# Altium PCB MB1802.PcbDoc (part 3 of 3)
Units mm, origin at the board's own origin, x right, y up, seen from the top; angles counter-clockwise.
Board outline 70 x 70 mm, 4 copper layers (Top Layer, Signal Layer 1, Signal Layer 2, Bottom Layer), stack 1.56 mm thick; 220 components, 159 nets, 974 pads, 563 vias.
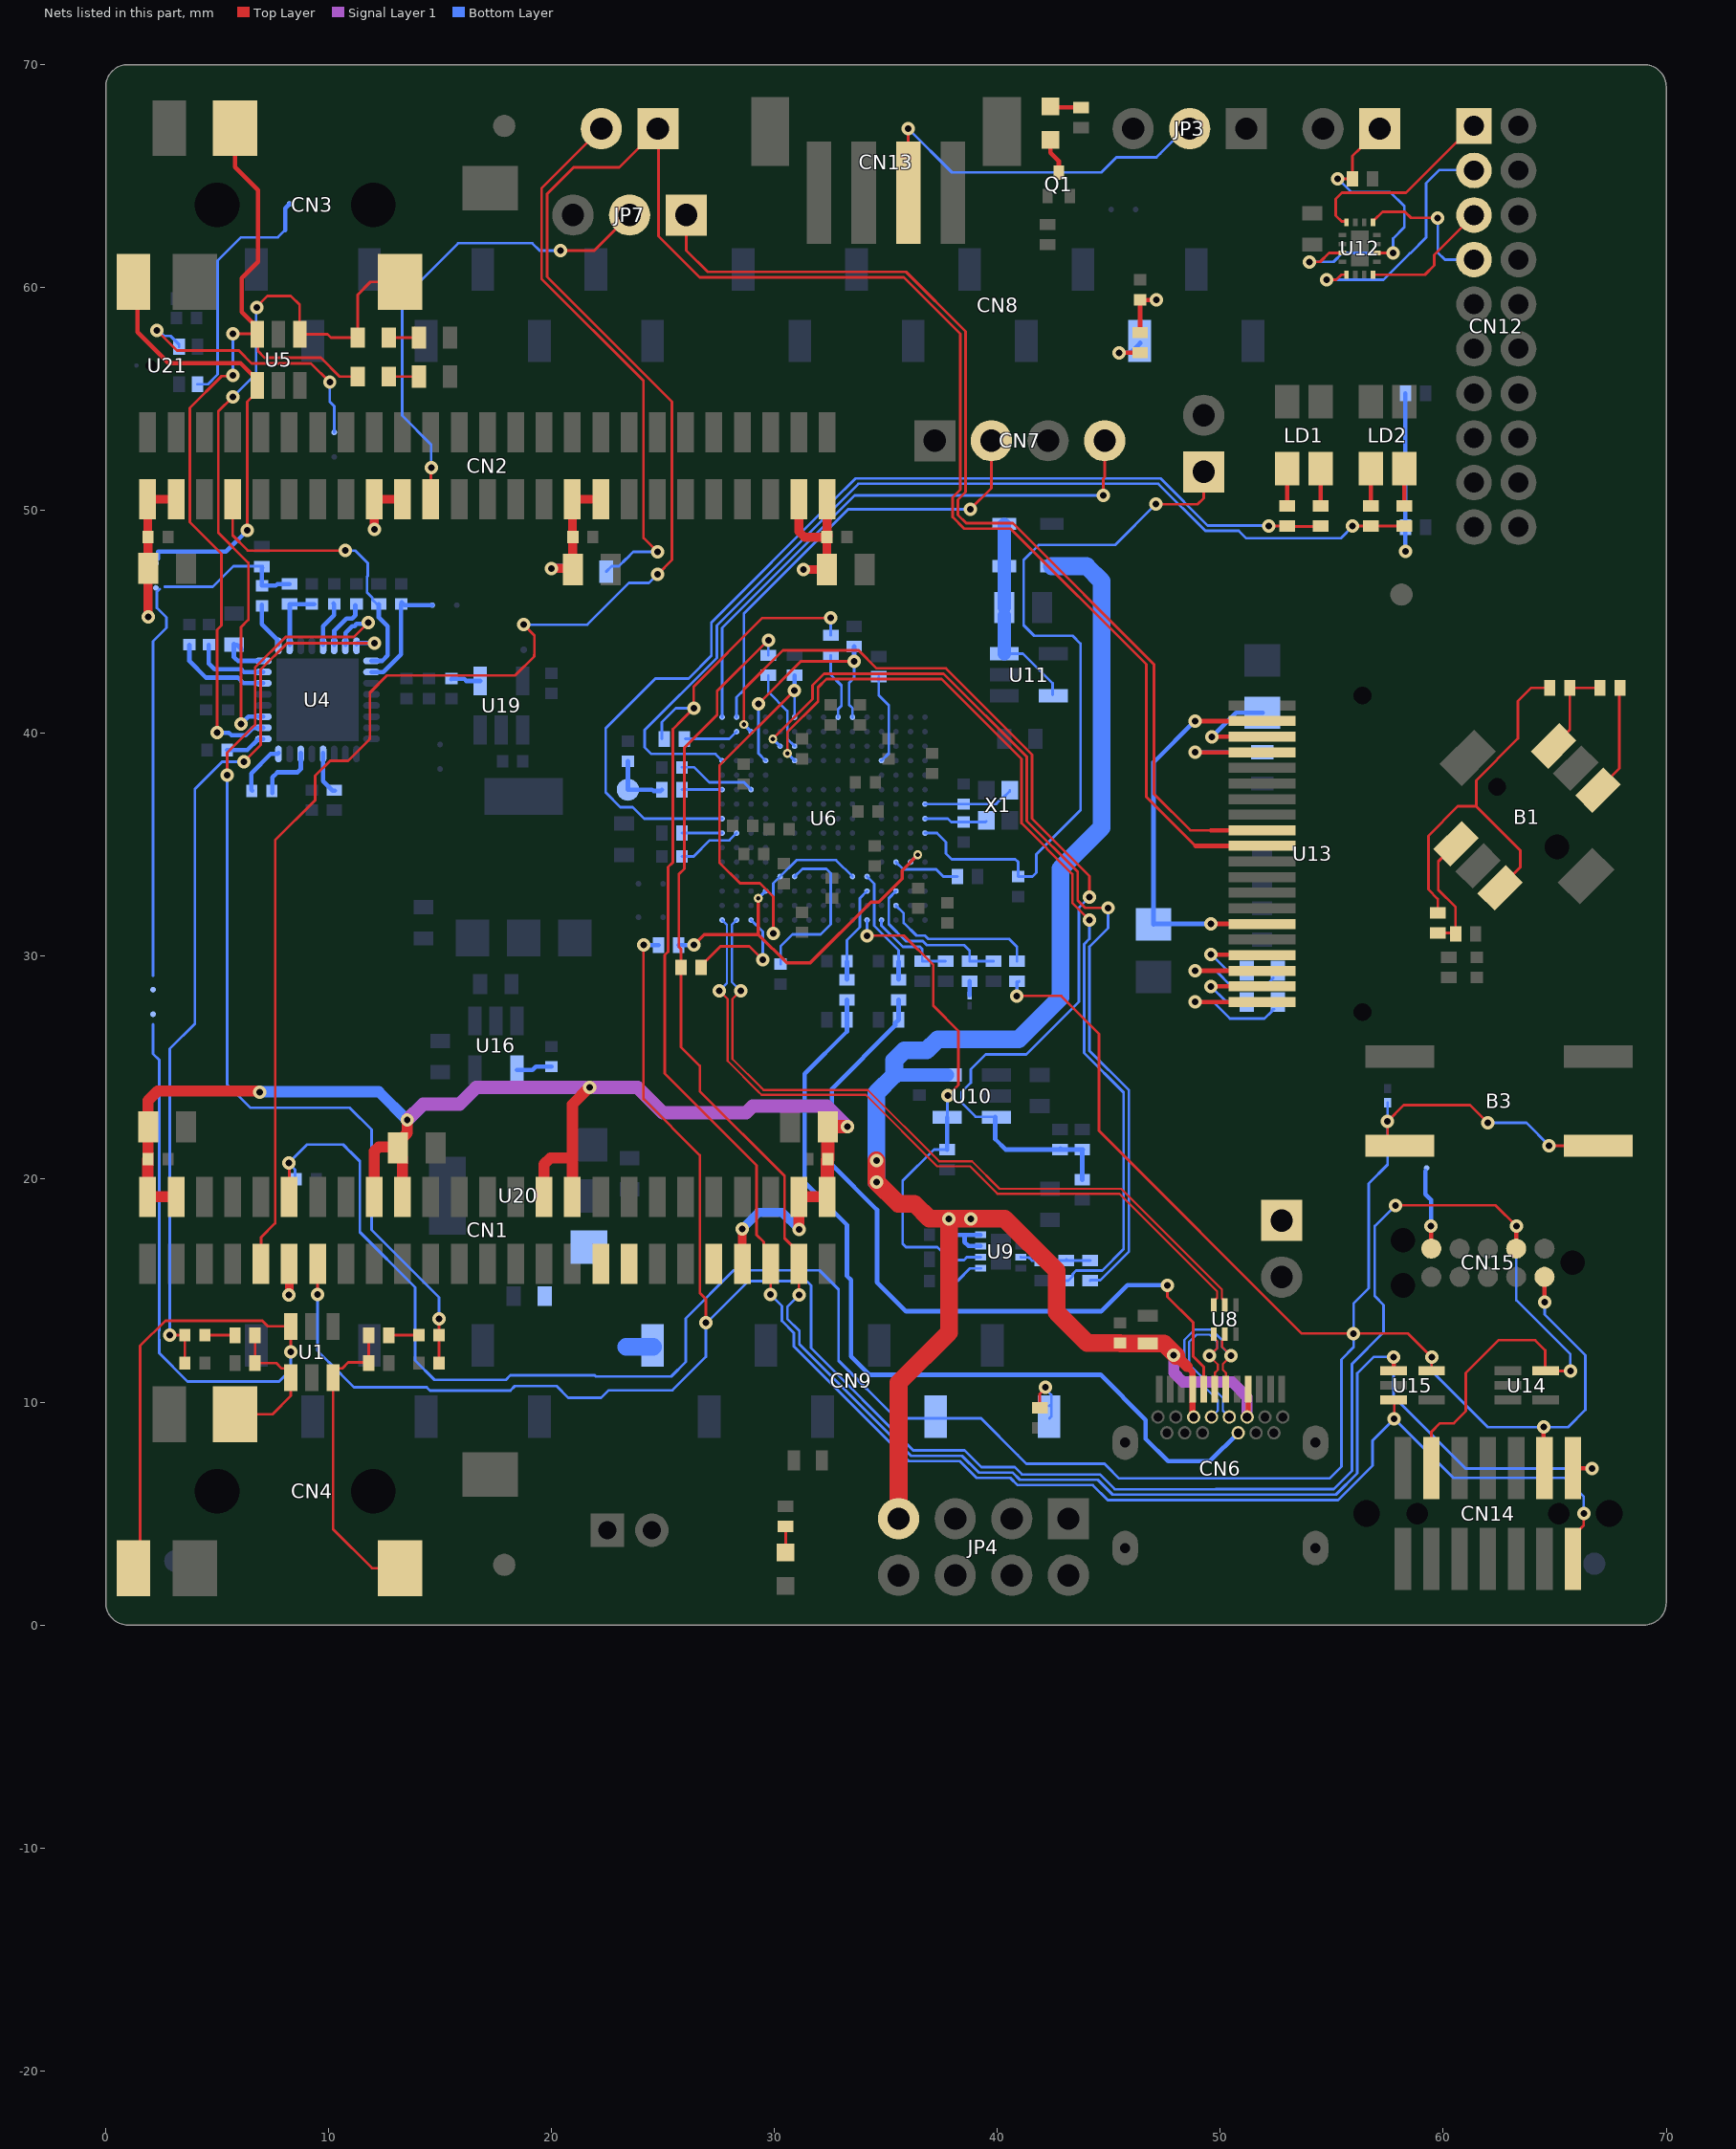
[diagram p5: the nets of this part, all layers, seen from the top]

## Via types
v1: diameter 0.6, hole 0.3, Top Layer to Bottom Layer, 509 vias
v2: diameter 0.4, hole 0.2, Top Layer to Bottom Layer, tented both sides, 54 vias

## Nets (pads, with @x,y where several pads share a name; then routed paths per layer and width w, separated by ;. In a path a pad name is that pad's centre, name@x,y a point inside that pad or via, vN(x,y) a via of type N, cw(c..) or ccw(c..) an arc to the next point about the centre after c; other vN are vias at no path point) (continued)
MCU.SWDIO: CN1.13 CN14.4 CN15.2 R16.2 U14.5 | length 118.2
  Top Layer w0.12: v1(9.5,14.825) 9.505,14.83 CN1.13@9.505,16.21 ; v1(24.125,30.5) 24.125,23.6 26.65,21.075 26.65,14.9 26.925,14.625 v1(26.925,13.555) ; v1(57.85,18.825) 62.35,18.825 v1(63.275,17.9) ; CN14.4@59.46,7.032 59.46,8.66 59.85,9.05 60.472,9.05 61.01,9.588 61.01,11.31 62.475,12.775 64.125,12.775 64.575,12.325 U14.5@64.575,11.35 ; U14.5@64.6,11.4 v1(65.7,11.4)
  Top Layer w0.2: CN15.2@63.275,16.885 v1(63.275,17.9)
  Bottom Layer w0.12: v1(9.5,14.825) 9.5,12.3 9.72,12.08 9.72,12.076 10.001,11.795 10.005,11.795 11.13,10.67 14.401,10.67 14.551,10.52 18.156,10.52 18.353,10.717 20.222,10.717 20.749,10.19 22.226,10.19 22.566,10.53 25.423,10.53 26.925,12.032 v1@26.925,13.525 ; v1(26.925,13.555) v1@26.925,13.525 ; v1(57.85,18.825) 56.925,17.9 56.925,14.75 57.325,14.35 57.325,13.128 55.905,11.708 55.905,6.909 55.091,6.095 49.794,6.095 49.789,6.09 45.267,6.09 44.602,6.755 41.102,6.755 40.777,7.08 39.281,7.08 38.526,7.835 36.219,7.835 31.635,12.419 31.635,15.24 31.445,15.43 28.83,15.43 v1@26.925,13.525 ; v1(63.275,17.9) 63.275,14.575 65.7,12.15 v1(65.7,11.4)
  Bottom Layer w0.2: v1(24.125,30.5) R16.2@24.8,30.5
MCU.VCP_RX: CN1.45 CN14.13 R21.2 R57.2 U15.3 | length 88.9
  Top Layer w0.12: v1(29.825,14.825) CN1.45@29.825,16.21 29.513,16.522 29.513,17.187 29.2,17.5 29.2,20.625 25.08,24.745 25.08,30.051 25.23,30.201 25.23,34.001 25.44,34.211 25.44,40.19 25.875,40.625 v1(26.375,41.125) 26.375,42.1 29.45,45.175 v1(32.525,45.175) ; U15.3@57.75,10.1 57.8,10.05 v1(57.8,9.25) ; CN14.13@65.81,2.968 65.81,3.993 66.08,4.263 66.088,4.263 66.3,4.475 v1(66.3,5)
  Bottom Layer w0.12: R57.2@24.95,39.75 24.95,40.5 25.575,41.125 v1(26.375,41.125) ; v1(29.825,14.825) 30.335,14.315 30.335,13.64 30.875,13.1 30.875,12.5 36.025,7.35 38.311,7.35 39.061,6.6 40.578,6.6 40.903,6.275 44.275,6.275 44.95,5.6 55.275,5.6 56.825,7.15 56.825,8.275 v1(57.8,9.25) 60.45,6.6 65.45,6.6 66.3,5.75 v1(66.3,5) ; R21.2@32.525,44.4 v1(32.525,45.175)
MCU.VCP_TX: CN1.47 CN14.14 R20.2 R58.2 U15.1 | length 84.8
  Top Layer w0.12: v1@29.725,44.2 27.425,41.9 27.425,40.825 25.955,39.355 25.955,33.926 25.71,33.681 25.71,30.415 25.8,30.325 R58.2@25.8,29.5 25.8,25.925 26.65,25.075 26.65,23.95 30.45,20.15 30.45,17.35 30.75,17.05 30.78,17.05 31.095,16.735 31.095,14.805 v1(31.1,14.8)
  Top Layer w0.2: U15.1@57.775,11.35 v1(57.775,12.025) ; CN14.14@65.81,7.032 66.668,7.032 v1(66.675,7.025)
  Bottom Layer w0.12: R20.2@29.725,43.5 v1(29.725,44.175) ; v1(31.1,14.8) 30.575,14.275 30.575,13.739 31.115,13.199 31.115,12.599 36.124,7.59 38.41,7.59 39.16,6.84 40.677,6.84 41.002,6.515 44.502,6.515 45.167,5.85 55.186,5.85 56.145,6.809 56.145,11.295 56.875,12.025 v1(57.775,12.025) 57.775,10.25 61,7.025 v1(66.675,7.025)
MOD1: CN12.1 U12.16 | length 8.9
  Top Layer w0.12: U12.16@55.65,62.925 55.615,62.96 55.44,62.96 55.175,63.225 55.175,63.975 55.45,64.25 58.325,64.25 60.585,66.51 60.635,66.51 61.325,67.2 CN12.1@61.325,67.25
MOD2: CN12.2 U12.5 | length 11
  Top Layer w0.12: v1(54.775,60.35) 55.2,60.35 55.425,60.575 U12.5@55.65,60.575
  Bottom Layer w0.12: v1(54.775,60.35) 57.316,60.35 58.501,61.535 58.514,61.535 59.225,62.246 59.225,64.675 59.825,65.275 CN12.2@61.375,65.275
MOD3: CN12.3 U12.8 | length 5.9
  Top Layer w0.12: U12.8@56.85,60.575 59.175,60.575 59.587,60.987 59.587,61.462 CN12.3@61.375,63.25
MOD4: CN12.4 U12.13 | length 6.5
  Top Layer w0.12: U12.13@56.85,62.925 56.85,63 56.89,63.04 56.915,63.04 57.275,63.4 58.275,63.4 58.55,63.125 v1@59.725,63.125
  Bottom Layer w0.12: v1(59.75,63.125) 59.75,61.575 60.075,61.25 CN12.4@61.375,61.25
NetB1_1: B1.1 R3.1 R4.2 | length 5.5
  Top Layer w0.12: R3.1@59.75,31.05 60.5,31.05 R4.2@60.55,31 60.55,31.05 60.55,32.2 59.775,32.975 59.775,34.25 B1.1@60.575,35.05
NetB1_3: B1.3 R2.1 R3.2 | length 18.4
  Top Layer w0.12: R3.2@59.75,31.95 59.75,32.575 59.33,32.995 59.33,35.405 60.65,36.725 61.468,36.725 63.45,34.743 63.45,33.993 B1.3@62.525,33.068 ; 61.475,36.725 61.475,37.893 63.35,39.768 63.35,41.443 63.95,42.043 64.75,42.043 R2.1@64.775,42.018
NetB1_4: B1.4 R1.1 R2.2 | length 4.2
  Top Layer w0.12: B1.4@64.95,39.443 65.675,40.168 R2.2@65.675,42.043 R1.1@66.975,42.043
NetB1_6: B1.6 R1.2 | length 5
  Top Layer w0.12: B1.6@66.932,37.452 67.9,38.42 R1.2@67.9,42.068
NetC12_1: C12.1 R6.2 | length 1.3
  Top Layer w0.12: R6.2@12.7,13 C12.1@13.975,13
NetC12_2: C12.2 C14.2 U4.23 | length 45.9
  Top Layer w0.12: v1(5.45,38.125) 5.45,39.125 6.7,40.375 6.7,42.95 8.075,44.325 11.136,44.325 v1(11.783,44.972) ; v1(14.95,13.725) C12.2@14.95,13 14.95,11.825 C14.2@14.975,11.8
  Bottom Layer w0.12: v1(5.45,38.125) 5.45,24.25 6.5,23.2 10.95,23.2 11.925,22.225 11.925,17.725 14.95,14.7 v1(14.95,13.725)
  Bottom Layer w0.2: U4.23@10.755,43.975 10.755,44.505 11.055,44.805 11.158,44.805 11.26,44.907 11.718,44.907 v1(11.783,44.972)
NetC21_1: C21.1 R51.1 | length 1.3
  Top Layer w0.12: C21.1@12.7,56 R51.1@14.05,56
NetC21_2: C21.2 CN3.4 U4.10 U5.6 | length 38.9
  Top Layer w0.12: v1(5,40.025) 5,44.65 5.19,44.84 5.19,48.06 3.775,49.475 3.775,54.6 5.2,56.025 5.665,56.025 v1(5.7,56.06) ; v1(5.7,57.925) U5.6@6.799,57.925 ; U5.6@6.8,57.9 6.835,57.865 6.835,57.14 7.125,56.85 9.65,56.85 10.5,56 C21.2@11.3,56
  Top Layer w0.2: CN3.4@5.8,67.15 5.8,65.4 6.825,64.375 6.825,61.15 6.1,60.425 6.1,58.9 6.6,58.4 6.799,58.201 6.8,58.2 U5.6@6.8,57.9
  Bottom Layer w0.12: v1(5.7,56.06) v1(5.7,57.925)
  Bottom Layer w0.2: v1@5.075,40.025 5.525,40.025 5.641,39.909 6.281,39.909 6.622,40.25 U4.10@7.075,40.25
NetC22_1: C22.1 SB8.2 U4.26 | length 5.3
  Bottom Layer w0.2: U4.26@11.925,42.75 12.45,42.75 13.25,43.55 C22.1@13.25,45.8 ; C22.1@13.275,45.875 13.4,45.75 SB8.2@14.65,45.75
NetC23_1: C23.1 R52.1 | length 1.3
  Top Layer w0.12: C23.1@12.7,57.75 R52.1@14.05,57.75
NetC23_2: C23.2 CN3.6 U4.11 U5.4 | length 31.6
  Top Layer w0.12: v1(5.7,55.1) 5.05,54.45 5.05,49 6.4,47.65 6.4,45.1 6.065,44.765 v1(6.065,40.429) ; v1@6.75,59.125 7.25,59.625 8.3,59.625 8.7,59.225 U5.4@8.7,57.9 9.95,57.9 10.1,57.75 C23.2@11.3,57.75 11.3,59.175 11.3,59.675 11.875,60.25 CN3.6@13.2,60.25
  Bottom Layer w0.12: v1(5.7,55.1) 6.75,56.15 v1@6.75,59.125
  Bottom Layer w0.2: v1(6.065,40.429) 6.079,40.429 6.4,40.75 U4.11@7.075,40.75
  other v1: 6.775,59.1
NetC24_2: C24.2 U4.9 | length 1.8
  Bottom Layer w0.2: C24.2@5.45,39.25 6.35,39.25 6.85,39.75 U4.9@7.075,39.75
NetC25_1: C25.1 U4.8 | length 2.4
  Bottom Layer w0.2: C25.1@6.575,37.425 6.525,37.475 6.525,38.2 7.4,39.075 7.704,39.075 U4.8@7.754,39.125
NetC25_2: C25.2 U4.6 | length 2.9
  Bottom Layer w0.2: C25.2@7.475,37.325 7.475,38.025 7.7,38.25 8.6,38.25 8.755,38.405 U4.6@8.755,39.125
NetC26_1: C26.1 R53.1 R54.1 SB6.1 SB7.2 | length 24.7
  Bottom Layer w0.12: 2.125,29.125 2.125,29.575 ; 2.125,29.58 2.125,44.125 2.725,44.725 2.725,45.2 2.3,45.625 2.3,46.35 2.425,46.475 ; 2.65,46.575 4.8,46.575 5.725,47.5 R53.1@7.05,47.5
  Bottom Layer w0.2: R53.1@7.025,47.425 7.005,47.405 C26.1@7.005,46.625 7.625,46.625 7.7,46.7 R54.1@8.25,46.7
NetC26_2: C26.2 U4.17 | length 2.1
  Bottom Layer w0.2: C26.2@7,45.775 7,44.898 7.716,44.182 7.716,44.014 U4.17@7.755,43.975
NetC27_1: C27.1 R54.2 U4.18 | length 2.9
  Bottom Layer w0.2: R54.2@8.25,45.8 R54.2@8.275,45.8 ; U4.18@8.255,43.975 8.255,45.78 R54.2@8.275,45.8 ; C27.1@9.35,45.8 C27.1@9.25,45.8 R54.2@8.275,45.8
NetC28_2: C28.2 U4.15 | length 3.5
  Bottom Layer w0.2: C28.2@4.625,43.975 4.625,43.125 4.875,42.875 6.075,42.875 6.2,42.75 U4.15@7.075,42.75
NetC29_2: C29.2 U4.22 | length 2.3
  Bottom Layer w0.2: U4.22@10.255,43.975 10.255,44.605 10.8,45.15 11.05,45.15 11.2,45.3 C29.2@11.2,45.75
NetC30_2: C30.2 U4.21 | length 2.1
  Bottom Layer w0.2: U4.21@9.755,43.975 9.755,44.805 10.25,45.3 C30.2@10.25,45.8 C30.2@10.225,45.825
NetC31_2: C31.2 U4.16 | length 2.3
  Bottom Layer w0.2: C31.2@5.75,44 5.75,43.425 5.825,43.35 5.875,43.3 5.925,43.25 U4.16@7.075,43.25 ; C31.2@5.88,43.975 C31.2@6.1,43.755
NetC32_2: C32.2 U4.14 | length 4.5
  Bottom Layer w0.2: C32.2@3.755,43.975 3.755,43.245 4.5,42.5 5.925,42.5 6.173,42.252 7.073,42.252 U4.14@7.075,42.25
NetC36_2: C36.2 R12.2 TP1.1 | length 3
  Bottom Layer w0.2: C36.2@23.425,38.75 TP1.1@23.425,37.475 ; TP1.1@23.55,37.475 TP1.1@23.425,37.475 ; R12.2@24.95,37.475 24.894,37.419 24.569,37.419 24.512,37.475 TP1.1@23.425,37.475
NetC42_2: C42.2 U6.J14 | length 2.9
  Bottom Layer w0.12: C42.2@25.85,34.475 26.375,34.475 27.1,35.2 27.975,35.2 U6.J14@28.3,35.525
NetC45_2: C45.2 U9.1 | length 1.6
  Bottom Layer w0.12: C45.2@37.925,15.4 37.965,15.44 38.215,15.44 38.775,16 U9.1@39.25,16
NetC48_2: C48.2 U6.M10 | length 7.6
  Bottom Layer w0.12: C48.2@30.275,29.65 30.275,30.45 30.8,30.975 32.075,30.975 32.525,31.425 32.525,33.73 32.33,33.925 31.25,33.925 U6.M10@30.9,33.575
NetC49_2: C49.2 U6.F13 | length 3.5
  Bottom Layer w0.12: C49.2@25.85,38.475 26.4,38.475 27.075,37.8 28.625,37.8 U6.F13@28.95,37.475
NetC59_2: C59.2 D1.2 D2.2 U11.3 U11.5 | length 8.7
  Bottom Layer w0.12: U11.3@40.305,43.575 41.15,43.575 42.475,42.25 U11.5@42.475,41.725
  Bottom Layer w0.6: U11.3@40.305,43.575 C59.2@40.305,45.28 ; C59.2@40.305,45.65 D1.2@40.305,47.5 D2.2@40.305,49.37
NetC71_1: C71.1 U13.2 | length 4.1
  Top Layer w0.2: v1(49.575,28.65) U13.2@51.875,28.65
  Bottom Layer w0.12: v1(49.575,28.65) 50.25,27.975 C71.1@51.075,27.975
NetC71_2: C71.2 U13.1 | length 7
  Top Layer w0.2: v1(48.875,27.95) U13.1@51.875,27.95
  Bottom Layer w0.12: v1(48.875,27.95) 49.675,27.95 50.425,27.2 51.975,27.2 52.315,27.54 52.315,27.565 52.375,27.625 C71.2@52.4,27.625
NetC72_1: C72.1 U13.3 | length 6.9
  Top Layer w0.2: v1(48.875,29.35) U13.3@51.875,29.35
  Bottom Layer w0.12: v1(48.875,29.35) 48.885,29.34 49.81,29.34 50.5,28.65 52,28.65 52.315,28.965 C72.1@52.375,29.025
NetC72_2: C72.2 U13.4 | length 4.2
  Top Layer w0.2: v1(49.575,30.075) 51.85,30.075 U13.4@51.875,30.05
  Bottom Layer w0.12: v1@49.575,30.1 50.325,29.35 C72.2@51.175,29.35
NetC73_1: C73.1 U13.6 U13.19 | length 17.8
  Top Layer w0.2: v1(48.875,40.55) U13.19@51.875,40.55 ; v1(49.575,31.45) U13.6@51.875,31.45
  Bottom Layer w0.2: C73.1@47,31.425 47,38.7 v1@48.9,40.6 ; C73.1@47.025,31.475 47.05,31.45 v1(49.575,31.45)
NetC76_1: C76.1 U13.18 | length 5
  Top Layer w0.2: v1(49.625,39.85) U13.18@51.875,39.85
  Bottom Layer w0.2: v1(49.625,39.85) 50.7,40.925 C76.1@51.875,40.925 C76.1@51.9,40.925
NetC79_1: C79.1 U16.4 | length 1.6
  Bottom Layer w0.2: U16.4@18.45,24.9 19.15,24.9 19.3,25.05 C79.1@20,25.05
NetC82_2: C82.2 U19.4 | length 1.4
  Bottom Layer w0.2: C82.2@15.5,42.425 15.525,42.45 16.075,42.45 16.175,42.35 U19.4@16.8,42.35
NetC87_1: C87.1 C88.2 U4.24 | length 40.5
  Top Layer w0.12: v1(2.875,13) C88.2@3.55,13 C87.1@3.55,11.75 ; v1(6.2,38.725) 6.95,39.475 6.95,42.861 8.139,44.05 v1(12.05,44.05)
  Bottom Layer w0.12: v1(2.875,13) 2.875,25.85 4,26.975 4,37.5 5.225,38.725 v1(6.2,38.725)
  Bottom Layer w0.2: U4.24@11.255,44.004 11.255,44.009 11.296,44.05 v1(12.05,44.05)
NetC88_1: C88.1 R50.2 | length 1.3
  Top Layer w0.12: C88.1@4.45,13 R50.2@5.8,13
NetCN2_7: CN2.7 R55.1 U4.25 | length 13.6
  Top Layer w0.12: CN2.7@5.695,50.5 5.695,48.88 6.375,48.2 v1(10.75,48.2)
  Bottom Layer w0.12: v1(10.75,48.2) 11.187,48.2 11.75,47.637 11.75,47.06 11.72,47.03 11.72,46.33 11.96,46.09 11.96,45.995 12.155,45.8 R55.1@12.25,45.8
  Bottom Layer w0.2: U4.25@11.925,43.25 12.4,43.25 12.65,43.5 12.65,44.8 12.25,45.2 R55.1@12.25,45.8
NetCN3_2: CN3.2 SB7.1 U5.1 | length 20.3
  Top Layer w0.12: v1(6.35,49.1) 6.35,54.875 6.55,55.075 6.56,55.075 6.8,55.315 U5.1@6.8,55.6
  Top Layer w0.2: CN3.2@1.25,60.25 1.426,60.074 1.426,57.999 2.825,56.6 6.05,56.6 6.55,56.1 6.6,56.1 6.8,55.9 U5.1@6.8,55.6
  Bottom Layer w0.2: 2.35,47.825 2.35,48.15 5.4,48.15 v1(6.35,49.1)
NetCN4_2: CN4.2 SB6.2 U1.6 | length 40.9
  Top Layer w0.12: CN4.2@1.25,2.55 1.55,2.85 1.55,12.525 2.675,13.65 7.025,13.65 7.275,13.4 U1.6@8.3,13.4 v1(8.3,12.25)
  Bottom Layer w0.12: 2.125,26.95 2.125,25.625 2.4,25.35 2.4,13.204 2.395,13.199 2.395,12.801 2.4,12.796 2.4,12.2 3.675,10.925 7.775,10.925 8.3,11.45 v1(8.3,12.25)
NetCN4_4: CN4.4 R10.2 R50.1 U1.1 | length 6.9
  Top Layer w0.12: CN4.4@5.8,9.45 7.475,9.45 8.3,10.275 U1.1@8.3,11.1 8.3,11.27 8.06,11.51 7.89,11.51 7.65,11.75 R10.2@6.7,11.75 R50.1@6.7,13
NetCN4_6: CN4.6 R6.1 R7.1 U1.3 | length 13.7
  Top Layer w0.12: R6.1@11.75,13 11.8,12.95 R7.1@11.8,11.75 ; R7.1@11.775,11.775 10.875,11.775 10.61,11.51 10.44,11.51 10.2,11.27 U1.3@10.2,11.1 10.2,4.3 11.95,2.55 CN4.6@13.2,2.55
NetCN6_A5: CN6.A5 R11.1 R13.2 | length 34.1
  Top Layer w0.12: v1(47.625,15.225) 47.625,14.725 48.775,13.575 48.775,12.05 49.25,11.575 CN6.A5@49.25,10.58
  Bottom Layer w0.2: R13.2@35.57,28.05 R11.1@35.57,27.15 35.415,26.995 35.415,26.89 32.575,24.05 32.575,20.65 34.6,18.625 34.6,15.375 35.9,14.075 44.65,14.075 45.825,15.25 47.6,15.25 v1(47.625,15.225)
NetCN6_B5: CN6.B5 R14.2 R15.1 | length 38
  Bottom Layer w0.2: R14.2@33.25,28.05 R15.1@33.25,27.15 33.25,26.625 31.35,24.725 31.35,19.85 33.25,17.95 33.25,15.65 33.425,15.475 33.425,12.043 34.243,11.225 44.625,11.225 46.65,9.2 46.65,8.35 47.65,7.35 49.53,7.35 CN6.B5@50.8,8.62
NetCN8_8: CN8.8 R44.1 | length 2.1
  Top Layer w0.2: v1(45.45,57.075) R44.1@46.398,57.075
  Bottom Layer w0.2: v1(45.45,57.075) 45.988,57.075 46.398,57.485 CN8.8@46.398,57.525
NetCN9_1: CN9.1 R43.1 | length 2.6
  Top Layer w0.12: R43.1@41.9,9.75 41.9,10.365 42.15,10.615 v1(42.15,10.675)
  Bottom Layer w0.12: v1@42.175,10.65 42.175,10.571 42.417,10.329 42.417,9.35 CN9.1@42.334,9.267 ; CN9.1@42.325,9.825 CN9.1@42.35,9.85
NetCN13_3: CN13.3 JP3.2 | length 16.2
  Top Layer w0.12: v1(36,67.125) 36,65.25 CN13.3@36.075,65.175
  Bottom Layer w0.12: v1(36,67.125) 37.961,65.164 44.664,65.164 45.339,65.839 47.136,65.839 47.301,66.005 47.305,66.005 48.425,67.125 JP3.2@48.625,67.125
NetCN15_5: CN15.5 SB1.1 | length 3.6
  Top Layer w0.2: v1(59.45,17.9) 59.45,16.895 CN15.5@59.46,16.885
  Bottom Layer w0.2: 59.2,20.375 59.2,19.325 59.375,19.15 59.45,19.075 v1(59.45,17.9)
NetJP2_1: JP2.1 R45.2 U12.3 U12.10 | length 15.3
  Top Layer w0.12: v1(54,61.15) 54.475,61.15 54.875,61.55 U12.3@55.475,61.55 ; v1(55.25,64.875) R45.2@55.925,64.875 55.925,65.9 56.28,66.255 56.28,66.26 57.045,67.025 JP2.1@57.05,67.025 ; U12.10@57.025,61.55 57.675,61.55 v1@57.7,61.575
  Bottom Layer w0.12: v1(54,61.15) 55.075,61.15 55.475,61.55 v1@57.675,61.55 ; v1@55.275,64.875 55.875,64.275 57.625,64.275 58.25,63.65 58.25,62.7 57.75,62.2 v1(57.75,61.55)
NetJP6_2: JP6.2 R5.2 | length 24.9
  Top Layer w0.12: JP6.2@22.23,67.125 19.55,64.445 19.55,60.386 24.125,55.811 24.125,48.765 v1(24.75,48.14)
  Bottom Layer w0.12: R5.2@22.45,47.25 22.7,47.5 23.021,47.5 23.351,47.83 23.355,47.83 23.665,48.14 v1(24.75,48.14)
NetLD1_1: LD1.1 R35.1 | length 1.6
  Top Layer w0.12: R35.1@54.5,50.325 R35.1@54.525,50.3
  Top Layer w0.2: R35.1@54.5,50.325 LD1.1@54.5,51.875
NetLD1_2: LD1.2 R36.1 | length 1.6
  Top Layer w0.12: R36.1@52.975,50.275 R36.1@53,50.3
  Top Layer w0.2: R36.1@53,50.3 LD1.2@53,51.875
NetLD2_1: LD2.1 R37.1 | length 1.6
  Top Layer w0.12: R37.1@58.175,50.275 R37.1@58.25,50.35
  Top Layer w0.2: R37.1@58.25,50.35 LD2.1@58.25,51.875
NetLD2_2: LD2.2 R38.2 | length 1.7
  Top Layer w0.12: R38.2@56.75,50.25 R38.2@56.8,50.2
  Top Layer w0.2: R38.2@56.75,50.25 LD2.2@56.75,51.875
NetLD3_1: LD3.1 R41.2 | length 1.4
  Top Layer w0.2: LD3.1@42.375,68.125 42.425,68.075 R41.2@43.725,68.075
NetLD3_2: LD3.2 Q1.3 | length 1.6
  Top Layer w0.2: LD3.2@42.375,66.625 42.375,66.05 42.75,65.675 Q1.3@42.75,65.225
NetLD4_1: LD4.1 R48.1 | length 1.2
  Top Layer w0.12: LD4.1@30.5,3.25 R48.1@30.5,4.425
NetR12_1: R12.1 U6.F15 | length 1.8
  Bottom Layer w0.12: R12.1@25.85,37.475 U6.F15@27.65,37.475
NetR24_1: R24.1 U6.P3 | length 7.1
  Bottom Layer w0.12: U6.P3@35.45,32.275 35.795,31.93 35.795,31.499 36.369,30.925 36.739,30.925 36.889,30.775 40.525,30.775 40.875,30.425 R24.1@40.875,29.775
NetR25_1: R25.1 U6.J15 | length 1.8
  Bottom Layer w0.12: R25.1@25.85,35.525 U6.J15@27.65,35.525
NetR28_1: R28.1 U6.D4 | length 4.1
  Bottom Layer w0.12: R28.1@34.675,42.55 34.675,41.7 35.125,41.25 35.125,39.1 U6.D4@34.8,38.775
NetR31_1: R31.1 R32.1 R33.1 U9.7 | length 3.2
  Bottom Layer w0.12: U9.7@41.05,16.5 41.06,16.49 41.41,16.49 41.545,16.355 41.995,16.355 R33.1@42,16.35 ; R33.1@42.005,16.35 43.05,16.35 R31.1@43.1,16.4 ; R31.1@43.08,16.35 R32.1@44.155,16.35 R32.1@44.175,16.35
NetR46_2: R46.2 U13.17 | length 6
  Top Layer w0.2: v1(48.875,39.15) U13.17@51.875,39.15
  Bottom Layer w0.2: v1(48.875,39.15) 51.8,39.15 R46.2@51.825,39.175
NetR49_1: R49.1 U4.4 | length 2
  Bottom Layer w0.2: U4.4@9.755,39.125 9.755,37.85 10.18,37.425 R49.1@10.275,37.425
NetR57_1: R57.1 U6.B14 | length 2.4
  Bottom Layer w0.12: R57.1@26,39.75 27.975,39.75 U6.B14@28.3,40.075
NetR58_1: R58.1 U6.R13 | length 5.3
  Top Layer w0.12: R58.1@26.775,29.65 26.775,29.67 26.895,29.79 26.915,29.79 27.575,30.45 28.875,30.45 v1(29.475,29.85)
  Bottom Layer w0.12: U6.R13@28.95,31.625 29.47,31.105 29.47,30.826 29.475,30.821 v1(29.475,29.85)
NetSB3_1: SB3.1 U21.1 | length 11
  Bottom Layer w0.12: U21.1@4.114,55.662 4.587,55.662 5.025,56.1 5.025,61.2 6.075,62.25 7.725,62.25 8.05,62.575
  Bottom Layer w0.2: 8.05,62.575 8.05,63.55 SB3.1@8.25,63.75
NetSB4_1: SB4.1 U21.4 | length 12.4
  Top Layer w0.12: v1(2.3,58.075) 3.2,57.175 5.975,57.175 6.55,56.6 9.2,56.6 v1(10.05,55.75)
  Bottom Layer w0.12: v1(2.3,58.075) 2.36,58.075 2.61,57.825 2.906,57.825 3.292,57.439 U21.4@3.292,57.338 ; v1(10.05,55.75) 10.05,54.875 10.25,54.675 SB4.1@10.25,53.5
NRST: B3.1 B3.2 C15.2 CN1.12 CN9.3 CN14.12 CN15.10 R24.2 U3.1 U15.5 | length 141.5
  Top Layer w0.12: v1(8.225,20.725) 8.235,20.715 CN1.12@8.235,19.21 ; v1(40.875,28.22) 42.855,28.22 44.55,26.525 44.55,22.175 53.65,13.075 v1(55.975,13.075) 58.425,13.075 v1(59.475,12.025) U15.5@59.475,11.45 ; B3.2@57.475,21.7 57.5,21.725 v1(57.5,22.6) 58.225,23.325 61.2,23.325 v1(62,22.525) ; v1(64.75,21.5) B3.1@66.95,21.5 B3.1@66.975,21.5
  Top Layer w0.2: v1(64.5,8.875) 64.5,7.975 CN14.12@64.525,7.95 ; CN15.10@64.535,15.62 64.535,14.49 v1(64.55,14.475)
  Bottom Layer w0.12: v1@8.225,20.775 v1(8.225,20.725) 8.225,20.696 8.5,20.421 C15.2@8.5,20 ; v1@8.25,20.775 9.025,21.55 10.65,21.55 10.969,21.231 10.973,21.231 11.4,20.804 11.4,17.625 13.875,15.15 13.875,11.875 14.75,11 17.957,11 18.154,11.197 21.944,11.197 21.991,11.15 25.364,11.15 26.015,11.801 26.015,13.754 28.171,15.91 32.015,15.91 32.875,15.05 32.875,11.858 35.466,9.267 39.269,9.267 40.916,7.62 41.301,7.235 44.801,7.235 44.885,7.151 45.461,6.575 54.892,6.575 55.425,7.108 55.425,11.907 55.975,12.457 v1(55.975,13.075) 55.975,14.425 56.65,15.1 56.65,19.8 57.5,20.65 v1(57.5,22.6) U3.1@57.5,23.438 ; R24.2@40.95,28.85 R24.2@40.975,28.875 ; v1(59.475,12.025) 59.475,11.4 62,8.875 v1(64.5,8.875) 65.6,8.875 66.375,9.65 66.375,12.1 64.55,13.925 v1(64.55,14.475) ; v1(62,22.525) 63.725,22.525 v1(64.75,21.5)
  Bottom Layer w0.15: v1(40.875,28.22) R24.2@40.875,28.85
OLED.CS: CN1.9 JP6.1 U13.11 | length 122.6
  Top Layer w0.12: CN1.9@6.965,16.21 6.965,17.39 7.6,18.025 7.6,35.2 9.4,37 9.4,38.1 10.07,38.77 10.878,38.77 11.845,39.737 11.845,39.789 11.85,39.794 11.85,41.825 12.625,42.6 18.375,42.6 19.225,43.45 19.225,43.521 19.23,43.526 19.23,44.395 v1(18.75,44.875) ; v1(24.75,47.125) 25.4,47.775 25.4,54.875 19.8,60.475 19.8,64.2 20.99,65.39 23.035,65.39 JP6.1@24.77,67.125 24.8,67.095 24.8,62.3 26.64,60.46 35.801,60.46 38.335,57.926 38.335,50.935 37.985,50.585 37.985,49.701 38.501,49.185 40.59,49.185 46.675,43.1 46.675,37.15 48.875,34.95
  Top Layer w0.2: 48.875,34.95 U13.11@51.875,34.95
  Bottom Layer w0.12: v1(18.75,44.875) 21.6,44.875 23.475,46.75 24.375,46.75 v1(24.75,47.125)
OLED.RST: JP7.1 U13.12 | length 47.4
  Top Layer w0.12: JP7.1@26.04,63.75 26.04,61.66 27,60.7 35.9,60.7 38.575,58.025 38.575,50.825 38.225,50.475 38.225,49.8 38.6,49.425 40.689,49.425 47.025,43.089 47.025,37.275 48.65,35.65 49.575,35.65
  Top Layer w0.2: 49.575,35.65 U13.12@51.875,35.65
OSC32_IN: CN1.33
OSC32_OUT: CN1.35
OSC_OUT: CN1.41
PA12: CN2.21 JP7.2 | length 21.6
  Top Layer w0.12: CN2.21@14.585,50.5 14.585,51.91 v1(14.6,51.925) ; v1(20.4,61.66) 21.91,61.66 JP7.2@23.5,63.25
  Bottom Layer w0.12: v1(14.6,51.925) 14.6,52.95 13.3,54.25 13.3,59.475 15.81,61.985 19.14,61.985 19.465,61.66 v1(20.4,61.66)
STLK_LED: R37.2 R38.1 U6.D15 | length 45.2
  Top Layer w0.12: v1(55.925,49.3) R38.1@56.75,49.3 58.225,49.3 R37.2@58.25,49.325
  Bottom Layer w0.12: U6.D15@27.65,38.775 27.35,39.075 24.475,39.075 24.175,39.375 24.175,40.15 27.41,43.385 27.41,44.835 33.77,51.195 47.216,51.195 49.326,49.085 50.826,49.085 51.161,48.75 55.4,48.75 v1@55.925,49.275
STLK_NRST: C41.2 JP1.1 U6.J1 | length 33.9
  Top Layer w0.12: v1@47.125,50.275 48.975,50.275 49.25,50.55 JP1.1@49.25,51.73
  Bottom Layer w0.12: U6.J1@36.75,35.525 37.29,35.525 37.69,35.125 37.69,34.605 37.945,34.35 40.804,34.35 40.925,34.229 C41.2@40.925,33.575 41.575,33.575 41.75,33.75 41.75,34.575 43.725,36.55 43.725,44.025 43.375,44.375 41.65,44.375 41.175,44.85 41.175,47.775 41.85,48.45 45.275,48.45 v1(47.109,50.284)
STLK_OSC_IN: C39.1 U6.G1 X1.1 | length 4.1
  Bottom Layer w0.12: U6.G1@36.75,36.825 C39.1@38.48,36.825 39.93,36.825 40.055,36.95 40.055,36.955 40.185,37.085 40.235,37.085 40.55,37.4 X1.1@40.55,37.45
STLK_OSC_OUT: C40.2 U6.H1 X1.3 | length 2.8
  Bottom Layer w0.12: U6.H1@36.75,36.175 37.775,36.175 37.925,36.025 C40.2@38.48,36.025 39.425,36.025 39.475,36.025 X1.3@39.5,36.05
STLK_SWCLK: CN7.2 U6.A14 | length 20.4
  Top Layer w0.12: v1(38.775,50.05) 39.725,51 CN7.2@39.725,53.175
  Bottom Layer w0.12: U6.A14@28.3,40.725 28.3,41.625 28.625,41.95 28.625,45.371 33.304,50.05 v1(38.775,50.05)
STLK_SWDIO: CN7.4 U6.A15 | length 26
  Top Layer w0.12: v1@44.75,50.7 44.75,51.425 44.81,51.485 CN7.4@44.81,53.125
  Bottom Layer w0.12: U6.A15@27.65,40.725 27.65,43.525 27.65,44.736 33.589,50.675 v1(44.75,50.675)
STLK_UCPD_CC1_C: C37.1 R13.1 U6.M5 | length 5.2
  Bottom Layer w0.12: U6.M5@34.15,33.575 34.475,33.25 34.475,31.361 35.57,30.266 35.57,30.235
  Bottom Layer w0.125: C37.1@35.57,29.775 35.57,30.235
  Bottom Layer w0.2: R13.1@35.57,28.95 C37.1@35.57,29.775
STLK_UCPD_CC2_C: C38.1 R14.1 U6.N5 | length 4.3
  Bottom Layer w0.12: C38.1@33.25,29.775 33.25,30.725 33.825,31.3 33.825,32.6 U6.N5@34.15,32.925
  Bottom Layer w0.2: R14.1@33.25,28.95 C38.1@33.25,29.775
STLK_USB_CN_N: CN6.A7 CN6.B7 U8.2 | length 9.9
  Top Layer w0.1: U8.2@50.2,12.9 50.2,12.875 50.075,12.75 50.075,12.475 v1(50.475,12.075) 50.11,11.71 50.11,11.447 50.25,11.307 CN6.A7@50.25,10.58
  Bottom Layer w0.1: CN6.B7@49.6,9.33 49.89,9.62 49.89,10.09 48.38,11.6 48.38,12.791 48.834,13.245 49.616,13.245 50.073,12.789 50.073,12.477 v1(50.475,12.075)
STLK_USB_CN_P: CN6.A6 CN6.B6 U8.1 | length 8.9
  Top Layer w0.1: v1@49.508,12.067 49.89,11.685 49.89,11.447 49.75,11.307 CN6.A6@49.75,10.58 ; v1@49.678,12.238 49.855,12.415 49.855,12.736 49.791,12.8 49.775,12.8 49.725,12.85 U8.1@49.725,12.925
  Bottom Layer w0.1: v1(49.515,12.075) 49.853,12.412 49.853,12.697 49.525,13.025 48.925,13.025 48.6,12.7 48.6,11.691 50.11,10.181 50.11,9.62 CN6.B6@50.4,9.33
STLK_USB_N: U6.R14 U8.5 | length 33.6
  Top Layer w0.1: v1(28.485,28.45) 28.115,28.08 28.115,25.396 29.406,24.106 29.511,24 34.186,24 37.386,20.8 38.861,20.8 40.091,19.57 45.555,19.57 50.07,15.055 50.07,14.655 50.2,14.525 U8.5@50.2,14.35
  Bottom Layer w0.1: U6.R14@28.3,31.625 28.085,31.41 28.085,28.85 v1(28.485,28.45)
STLK_USB_P: U6.R15 U8.6 | length 33.6
  Top Layer w0.1: v1(27.525,28.45) 27.895,28.08 27.895,25.305 29.25,23.95 29.42,23.78 34.095,23.78 37.295,20.58 38.77,20.58 40,19.35 45.464,19.35 49.85,14.964 49.85,14.675 49.7,14.525 U8.6@49.7,14.35
  Bottom Layer w0.1: v1(27.525,28.45) 27.865,28.79 27.865,31.41 U6.R15@27.65,31.625
STLK_VCP_RX: R20.1 U6.C10 | length 3.7
  Bottom Layer w0.12: R20.1@29.725,42.6 29.725,41.937 29.725,41.85 30.575,41 30.575,39.75 U6.C10@30.9,39.425
STLK_VCP_TX: R21.1 U6.A7 | length 3
  Bottom Layer w0.12: R21.1@32.525,43.5 32.525,43.065 32.525,42.629 33.005,42.149 33.005,41.23 32.85,41.075 U6.A7@32.85,40.725
T_JTDI: R19.1 U6.L3 | length 3
  Bottom Layer w0.12: U6.L3@35.45,34.225 35.775,33.9 37.25,33.9 37.575,33.575 R19.1@38.2,33.575
T_PWR_EN: R34.2 R40.2 U6.R5 U9.2 U10.4 | length 22.3
  Top Layer w0.12: v1(34.15,30.925) 35.8,30.925 37.125,29.6 37.125,27.775 38.25,26.65 38.25,24.225 v1(37.775,23.75)
  Bottom Layer w0.12: v1(34.15,30.925) U6.R5@34.15,31.625 ; R40.2@37.75,21.325 37.15,21.325 35.75,19.925 35.75,17.1 35.9,16.95 37.3,16.95 37.56,16.69 37.655,16.69 37.85,16.495 R34.2@37.85,16.4 ; U10.4@37.76,22.79 37.76,23.735 v1(37.775,23.75) ; R34.2@37.975,16.375 38.5,16.375 38.625,16.5 U9.2@39.25,16.5
  Bottom Layer w0.2: R40.2@37.75,21.32 U10.4@37.75,22.775
T_PWR_EXT: R22.1 R23.1 U6.R4 | length 4.1
  Bottom Layer w0.12: U6.R4@34.8,31.625 34.8,31.375 35.758,30.418 36.533,30.418 36.625,30.325 R22.1@36.625,29.775 R23.1@37.675,29.775
T_PWR_INT: R29.2 R30.1 R39.2 U6.B13 U10.3 | length 46
  Top Layer w0.12: v2(28.625,40.4) 28.625,41.975 30.375,43.725 33.775,43.725 34.585,42.915 37.689,42.915 41.555,39.049 41.555,36.17 44.125,33.6 v1(44.125,32.65)
  Bottom Layer w0.12: U10.3@39.9,22.8 39.025,22.8 38.4,23.425 38.4,23.924 38.8,24.324 38.8,24.925 39.475,25.6 41.3,25.6 43.65,27.95 43.65,32.175 v1(44.125,32.65) ; R30.1@43.805,21.325 R30.1@43.825,21.325
  Bottom Layer w0.15: v2(28.625,40.4) U6.B13@28.95,40.075
  Bottom Layer w0.2: U10.3@39.9,22.8 39.9,21.8 40.375,21.325 R39.2@42.8,21.325 ; R39.2@42.825,21.375 42.875,21.325 R30.1@43.805,21.325 ; R29.2@43.805,19.975 43.805,21.305 R30.1@43.825,21.325
T_PWR_LED: R35.2 R36.2 U6.H15 | length 47.1
  Top Layer w0.12: v1(52.175,49.3) R36.2@53,49.3 ; R36.2@53.025,49.275 54.475,49.275 R35.2@54.5,49.3
  Bottom Layer w0.12: 26.425,36.175 24.15,36.175 23.638,36.687 23.088,36.687 22.425,37.35 22.425,40.225 24.66,42.46 26.146,42.46 27.17,43.484 27.17,44.97 32.61,50.41 33.635,51.435 47.315,51.435 49.425,49.325 v1@52.2,49.325 ; 26.428,36.178 26.43,36.175 U6.H15@27.65,36.175
T_PWR_SEL1: R31.2 U6.D10 | length 42.1
  Top Layer w0.12: v2(30.575,39.1) 30.575,40.05 31.95,41.425 31.95,42.061 32.324,42.435 37.49,42.435 41.075,38.85 41.075,35.971 43.36,33.686 43.36,32.39 44.125,31.625 v1(44.13,31.625)
  Bottom Layer w0.12: R31.2@43.08,15.45 43.175,15.45 43.37,15.645 43.37,15.74 43.53,15.9 44.7,15.9 45.66,16.86 45.66,23.89 43.89,25.66 43.89,30.54 44.13,30.78 v1(44.13,31.625)
  Bottom Layer w0.15: v2(30.575,39.1) U6.D10@30.9,38.775
T_PWR_SEL2: R32.2 U6.C11 | length 42.6
  Top Layer w0.12: v2(29.925,39.75) 31.71,41.535 31.71,42.16 32.225,42.675 37.589,42.675 41.315,38.949 41.315,36.071 43.6,33.786 43.6,32.496 43.926,32.17 44.275,32.17 44.276,32.171 v1(44.957,32.171)
  Bottom Layer w0.12: R32.2@44.155,15.45 44.17,15.465 44.615,15.465 45.9,16.75 45.9,23.989 44.13,25.759 44.13,30.43 44.957,31.257 v1(44.957,32.171)
  Bottom Layer w0.15: v2(29.925,39.75) U6.C11@30.25,39.425
T_SWCLK: R18.1 U6.A10 U6.M6 U6.M11 | length 22.2
  Top Layer w0.12: v1(29.95,31.025) 29.95,32.675 29.35,33.275 28.455,33.275 27.53,34.2 27.53,38.555 v1(30.9,41.925)
  Bottom Layer w0.12: v1(29.95,31.025) 29.95,31.57 29.945,31.575 29.945,33.27 U6.M11@30.25,33.575 30.988,34.313 32.762,34.313 U6.M6@33.5,33.575 ; U6.A10@30.9,40.725 v1(30.9,41.925)
  Bottom Layer w0.2: v1(30.9,41.925) R18.1@30.9,42.6
T_SWDIO: R16.1 U6.L2 U6.N12 | length 16.2
  Top Layer w0.15: v1(26.375,30.5) 26.85,30.975 29.275,30.975 ; v2(29.275,32.6) 29.275,30.975 ; v2(36.425,34.55) 35.725,33.85 35.725,33.475 34.675,32.425 34.325,32.425 31.6,29.7 30.55,29.7 29.275,30.975
  Bottom Layer w0.15: v2(29.275,32.6) U6.N12@29.6,32.925 ; U6.L2@36.1,34.225 v2(36.425,34.55)
  Bottom Layer w0.2: R16.1@25.7,30.5 v1(26.375,30.5)
T_SWO: R17.1 U6.A6 U6.D12 | length 11.1
  Top Layer w0.12: v1(29.275,41.325) 31.18,43.23 v1(33.575,43.23)
  Bottom Layer w0.12: v1(29.275,41.325) 29.275,39.1 U6.D12@29.6,38.775 ; U6.A6@33.5,40.725 33.5,41.125 33.345,41.28 33.345,42.27 33.575,42.5 v1(33.575,43.23)
  Bottom Layer w0.2: v1(33.575,43.23) R17.1@33.575,43.9
T_VCC: LNK1.2 R26.2 | length 0.6
  Bottom Layer w0.2: LNK1.2@38.75,28.25 R26.2@38.75,28.875
T_VCC_AIN: R26.1 R27.1 U6.N3 | length 7.3
  Bottom Layer w0.12: U6.N3@35.45,32.925 35.125,32.6 35.125,31.443 35.893,30.675 36.65,30.675 36.825,30.5 38.5,30.5 38.75,30.25 R26.1@38.75,29.775 R27.1@39.825,29.775
V1: C1.1 C2.2 C3.2 C4.2 C5.2 C6.2 C7.2 C8.1 C9.2 C10.2 C11.2 C69.1 CN1.2 CN1.4 CN1.11 CN1.18 CN1.20 CN1.30 CN1.32 CN1.43 CN1.48 CN1.50 CN2.1 CN2.3 CN2.17 CN2.19 CN2.31 CN2.33 CN2.47 CN2.49 JP5.1 R5.1 R8.2 R9.2 R44.2 | length 99.7
  Top Layer w0.12: R44.2@46.398,58.027 R44.2@46.425,58
  Top Layer w0.2: R44.2@46.398,57.975 46.398,58.027 C69.1@46.398,59.44 47.115,59.44 v1(47.125,59.45)
  Top Layer w0.4: v1(1.9,45.225) C4.2@1.9,47.4 C9.2@1.9,48.8 1.885,48.815 CN2.1@1.885,50.5 CN2.3@3.155,50.5 CN2.3@3.125,50.47 ; v1(8.225,14.8) 8.235,14.81 CN1.11@8.235,16.21 ; v1(12.05,49.15) 12.045,49.155 CN2.17@12.045,50.5 CN2.19@13.315,50.5 ; v1(20,47.4) 20.9,47.4 C5.2@20.95,47.35 C10.2@20.95,48.75 ; C10.2@20.95,48.8 C10.2@20.95,48.75 ; C10.2@20.975,48.725 C10.2@20.95,48.75 ; CN2.33@22.205,50.5 CN2.31@20.935,50.5 20.935,48.765 C10.2@20.95,48.75 ; v1(28.55,17.775) 28.555,17.77 CN1.43@28.555,16.21 ; CN2.47@31.095,50.5 31.095,49.055 31.35,48.8 32.325,48.8 C11.2@32.365,48.84 ; v1(31.3,47.35) C6.2@32.35,47.35 ; C6.2@32.25,47.175 32.35,47.275 C11.2@32.35,48.8 ; CN2.49@32.365,50.5 C11.2@32.365,48.84 ; C11.2@32.4,48.875 C11.2@32.365,48.84
  Top Layer w0.5: C2.2@1.9,22.35 C2.2@1.9,22.5 ; CN1.4@3.155,19.21 CN1.2@1.885,19.21 1.885,20.885 C7.2@1.9,20.9 C2.2@1.9,22.5 ; v1(6.9,23.9) 6.873,23.9 6.823,23.95 2.325,23.95 1.9,23.525 C2.2@1.9,22.5 ; CN1.18@12.045,19.21 12.045,21.245 12.25,21.45 13.05,21.45 13.05,21.2 13.315,20.935 CN1.20@13.315,19.21 ; C1.1@13.1,21.4 13.1,21.65 13.525,22.075 v1(13.525,22.65) ; CN1.30@19.665,19.21 19.665,20.665 19.95,20.95 20.935,20.95 ; CN1.32@20.935,19.21 20.935,20.95 ; v1@21.681,24.106 20.935,23.36 20.935,20.95 ; v1(31.1,17.75) 31.095,17.755 CN1.48@31.095,19.21 CN1.50@32.365,19.21
  Top Layer w0.6: CN1.50@32.365,19.21 32.365,20.865 C8.1@32.4,20.9 C3.2@32.4,22.35 v1(33.275,22.35)
  Signal Layer 1 w0.6: v1(13.525,22.65) 14.25,23.375 15.875,23.375 16.625,24.125 v1(21.7,24.125) 23.85,24.125 25,22.975 28.725,22.975 29.025,23.275 32.35,23.275 v1(33.275,22.35)
  Bottom Layer w0.2: v1(58.3,48.17) R9.2@58.3,49.25 R8.2@58.3,55.25
  Bottom Layer w0.4: v1@20.05,47.375 20.075,47.4 20.93,47.4 21.05,47.28 R5.1@21.05,47.25 ; v1(28.55,17.775) 29.275,18.5 30.35,18.5 v1(31.1,17.75)
  Bottom Layer w0.5: v1(6.9,23.9) 6.919,23.919 6.99,23.919 6.996,23.925 12.25,23.925 v1(13.525,22.65)
VBUS_STLK: C35.1 C44.2 C46.2 CN6.A4 CN6.A9 CN6.B4 CN6.B9 D1.1 JP4.7 U7.1 U9.3 U9.4 U10.5 | length 84.6
  Top Layer w0.2: CN6.B9@48.75,9.375 CN6.B9@48.775,9.35 ; CN6.B4@51.1,9.375 51.11,9.375 51.25,9.515 CN6.A9@51.25,10.58
  Top Layer w0.28: 48.5,11.6 48.75,11.35 CN6.A4@48.75,10.58 CN6.B9@48.75,9.375
  Top Layer w0.5: v1(47.91,12.1) 47.929,12.081 48.019,12.081 48.5,11.6
  Top Layer w0.8: v1(34.575,19.875) 35.55,18.9 36.275,18.9 36.95,18.225 v1(37.825,18.225) ; v1@34.575,19.925 v1(34.575,20.835) ; JP4.7@35.565,4.77 35.565,10.865 37.825,13.125 v1(37.825,18.225) ; C35.1@45.475,12.65 44.025,12.65 42.65,14.025 42.65,15.9 40.325,18.225 v1(37.825,18.225) ; C35.1@45.5,12.65 45.525,12.625 U7.1@46.75,12.625 47.475,12.625 v1@48.019,12.081
  Signal Layer 1 w0.5: v1(47.91,12.1) 47.91,11.315 48.325,10.9 50.525,10.9 51.2,10.225 CN6.B4@51.2,9.33
  Bottom Layer w0.2: v1(37.825,18.225) 37.85,18.2 C44.2@37.85,17.5 38.525,17.5 ; U9.3@39.25,17 38.7,17 38.525,17.175 38.525,17.5 ; U9.4@39.25,17.5 38.525,17.5
  Bottom Layer w0.6: 35.675,24.675 C46.2@36.5,24.675 U10.5@37.75,24.675
  Bottom Layer w0.8: v1(34.575,19.875) v1(34.575,20.835) 34.575,23.875 35.375,24.675 35.375,25.325 35.825,25.775 36.825,25.775 37.325,26.275 40.95,26.275 42.825,28.15 42.825,33.925 44.675,35.775 44.675,46.825 44,47.5 D1.1@42.445,47.5
  other v1: 38.8,18.225
VIN: C83.2 CN9.8 U20.3 | length 1.2
  Bottom Layer w0.8: 23.35,12.475 23.353,12.472 CN9.8@24.554,12.472
pads on no net: B1.NPTH1 B1.NPTH2 CART_4L.1 CN1.3 CN1.5 CN1.8 CN1.10 CN1.16 CN1.19 CN1.21 CN1.23 CN1.27 CN1.39 CN2.4 CN2.5 CN2.6 CN2.16 CN2.18 CN2.23 CN2.36 CN3.5 CN3.7 CN3.MT1 CN3.MT2 CN4.5 CN4.7 CN4.MT1 CN4.MT2 CN6.A2 CN6.A3 CN6.A8 CN6.A10 CN6.A11 CN6.B2 CN6.B3 CN6.B8 CN6.B10 CN6.B11 CN12.8 CN12.9 CN13.0 CN14.0 CN14.1 CN14.2 CN15.7 CN15.11 CN15.12 CN15.13 MIRE-1.1 MIRE-2.1 MIRE-3.1 MIRE-4.1 MIRE-5.1 MIRE-6.1 U4.19 U4.20 U6.A1 U6.A2 U6.A3 U6.A4 U6.A5 U6.A8 U6.A9 U6.A11 U6.A12 U6.A13 U6.B1 U6.B2 U6.B3 U6.B4 U6.B5 U6.B6 U6.B7 U6.B8 U6.B9 U6.B10 U6.B11 U6.B12 U6.B15 U6.C2 U6.C3 U6.C4 U6.C12 U6.C13 U6.C14 U6.C15 U6.D1 U6.D2 U6.D3 U6.D11 U6.D13 U6.D14 U6.E1 U6.E2 U6.E3 U6.E4 U6.E12 U6.E13 U6.E14 U6.E15 U6.F1 U6.F4 U6.F14 U6.G4 U6.G14 U6.G15 U6.H2 U6.H3 U6.H4 U6.H14 U6.J2 U6.J3 U6.J4 U6.K1 U6.K2 U6.K3 U6.K12 U6.K13 U6.K14 U6.K15 U6.L1 U6.L12 U6.L13 U6.L14 U6.L15 U6.M2 U6.M3 U6.M4 U6.M7 U6.M12 U6.M13 U6.M14 U6.M15 U6.N2 U6.N4 U6.N6 U6.N7 U6.N11 U6.N15 U6.P2 U6.P4 U6.P5 U6.P6 U6.P7 U6.P8 U6.P9 U6.P10 U6.P11 U6.P12 U6.P13 U6.P14 U6.P15 U6.R2 U6.R3 U6.R6 U6.R7 U6.R8 U6.R9 U6.R10 U6.R11 U6.R12 U8.4 U11.4 U12.17 U13.H1 U21.6

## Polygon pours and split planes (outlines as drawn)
GND on Bottom Layer "GND_L04" (solid, remove dead copper, pour order 19): 0,0 0,70 70,70 70,0
3V6 on Bottom Layer "5V_L04_P-001" (solid, pour order 18): 16.84,23.675 14.866,23.675 14.59,23.951 14.59,25.095 16.84,25.095
5V_VIN on Bottom Layer "5V_VIN_L04" (solid, pour order 11): 16.25,16.5 16.25,16 20.25,16 20.25,18 20.75,18.5 24,18.5 24,20 20.75,20 20.25,20.5 20.25,22.5 18.5,22.5 18,23 15.5,23 14.5,22 14.5,16.5
VIN on Bottom Layer "VIN_L04" (solid, pour order 10): 19.5,15 19.5,15.25 20,15.75 20.5,15.75 20.75,16 20.75,17.25 21,17.5 23,17.5 24.75,15.75 24.75,11.75 20.5,11.75 19.5,12.75
3V3 on Bottom Layer "3V3_L04_P-001" (solid, pour order 9): 19.5,32.25 22,32.25 22,36 21.5,36 21.5,40.5 18.5,40.5 18.5,38 17,38 17,36 15.5,36 15.5,32.25 18,32.25 18,30.5 19.5,30.5
5V on Bottom Layer "5V_L04_P-001" (solid, pour order 8): 16.75,26.75 15.75,26.75 13.75,28.75 13.75,31 14.5,31 14.75,31.25 15,31.5 17,31.5 17,28.25 16.75,28
5V on Bottom Layer "5V_L04" (solid, pour order 6): 32.75,10 34.5,8.25 34.5,7.25 34.25,7 32.5,7 31.75,7.75 31.75,10
VBUS_STLK on Bottom Layer "VBUS_STLK_L01" (solid, pour order 2): 39.45,16.9 39.45,18.3 39.25,18.5 37.5,18.5 37.5,17.35 37.8,17.05 38.45,17.05 38.6,16.9
5V_STLK on Bottom Layer "5V_STLK_L04" (solid, pour order 3): 40.85,16.9 40.85,18.1 41.25,18.5 42.85,18.5 43.55,19.2 44.05,19.2 44.5,18.75 44.5,17.25 44.15,16.9 41.9,16.9
5V_STLK on Signal Layer 1 "5V_STLK_L02" (solid, remove dead copper, pour order 13): 42.5,3.75 42.5,17.5 43.5,18.5 44.75,18.5 45.25,18 45.25,4.5 44.5,3.75
GND on Signal Layer 1 "GND_L02_P021" (solid, remove dead copper, pour order 21): 64.5,70 64.5,48.5 64,48 61.25,48 61.25,15 57.75,11.5 46.75,11.5 45.5,10.25 45.5,0 70,0 70,69.75 69.75,70
GND on Signal Layer 1 "GND_L02_P020" (solid, remove dead copper, pour order 20): 0,70 0,46.5 1.75,46.5 17.25,62 59.75,62 60.25,62.5 60.25,70
5V_VIN on Signal Layer 1 "5V_VIN_L02" (solid, remove dead copper, pour order 12): 42,17.75 43.25,19 54,19 57.75,22.75 57.75,47.25 55.25,49.75 43.25,49.75 43.25,31 46.5,31 51,26.5 51,23.25 36.75,23.25 16.5,23.25 16,22.75 16,20.75 19.5,17.25 19.5,12.5 21.75,10.25 34.5,10.25 35.25,9.5 35.25,7.25 36,6.5 39,6.5 39.25,6.25 39.25,4.25 39.75,3.75 41.5,3.75 42,4.25
5V on Signal Layer 1 "5V_L02_P-001" (solid, remove dead copper, pour order 7): 10,14 10,1 44.25,1 44.75,1.5 44.75,3 44.25,3.5 35,3.5 34.75,3.75 34.75,9.25 34.25,9.75 21.25,9.75 19,12 19,17 15.5,20.5 15.5,23 16.25,23.75 50.5,23.75 50.5,26.5 46.5,30.5 10.5,30.5 7.75,27.75 7.75,16.25
V1 on Signal Layer 1 "3V3_MCU_L02" (solid, remove dead copper, pour order 14): 1,45 17.5,61.5 60.75,61.5 60.75,15.5 57.5,12.25 46.75,12.25 46.75,18.5 54.25,18.5 58.25,22.5 58.25,47.5 57.75,48 57.75,57 57,57.75 36.75,57.75 32,53 32,47.25 27.5,42.75 27.5,31 10.25,31 7.25,28 7.25,16.25 9.5,14 9.5,1 1,1
3V3_STLK on Signal Layer 1 "3V3_STLK_L02" (solid, remove dead copper, pour order 4): 30.5,45 32.5,47 32.5,52.5 37.25,57.25 51.75,57.25 56.75,57.25 57.25,56.75 57.25,52.25 55.25,50.25 43.25,50.25 42.75,49.75 42.75,31 28,31 28,42.5
GND on Top Layer "GND_L01" (solid, remove dead copper, pour order 17): 0,0 0,70 70,70 70,0
5V on Top Layer "5V_L01" (solid, pour order 16): 49,25.25 56,25.25 56,24.75 55,23.75 49,23.75
5V on Top Layer "g" (solid, pour order 5): 32,7 32,8.25 32.38,8.63 34.12,8.63 34.5,8.25 34.5,6.25 33.5,6.25 32.75,7
GND on Signal Layer 2 "GND_L01_P-001" (solid, remove dead copper, pour order 0): 0,70 70,70 70,0 69.5,0.5 0,0.5

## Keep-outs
Keep-Out Layer:
  rectangle: 62.5,45.375 68.625,47.125

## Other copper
Top Layer:
  text "1" at 62.764,45.607 h2
Signal Layer 1:
  text "2" at 64.198,45.607 h2
Signal Layer 2:
  text "3" at 65.831,45.618 h2
  text ".Layer_Name" at 0.025,-14.036 h3
  text ".G2" at 41.725,-14.042 h3
Bottom Layer:
  text "4" at 67.431,45.609 h2

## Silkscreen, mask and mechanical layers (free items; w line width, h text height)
Top Overlay:
  lines w0.15: 2.5,13.75 4.6,13.75 5.1,13.25 5.1,12.5 5.35,12.25
  text "AUDIO_OUT" at 7.8,67.75 h1.5
  text "STLK" at 60.259,51.975 h1.4 r90
  text "PW_ST" at 51.951,51.325 h1.4 r90
  text "RESERVED" at 37.675,50.567 h1.5
  text "J" at 40.2,14.3 h12 r90
  text "MB1802B" at 41.4,13.275 h2 r90
  text "VBUS_STLK" at 35.951,6.501 h1.4 r90
  text "5V_EXT" at 38.451,6.5 h1.4 r90
  text "5VVIN" at 41.084,6.5 h1.4 r90
  text "5V_STLK" at 43.551,6.5 h1.4 r90
  text "AUDIO_IN" at 5.6,0.975 h1.5
Bottom Overlay:
  text "D10 CS / PWM" at 34.7,70.141 h1.5 r90
  text "D11 MOSI / PWM" at 37.4,70.141 h1.5 r90
  text "D13 SCK" at 41.783,67.484 h1.5 r90
  text "D9 MISO" at 39.183,67.352 h1.5 r90
  text "D9 PWM" at 31.483,67.159 h1.5 r90
  text "GND" at 44.1,64.9 h1.4 r90
  text "D14 / SDA" at 49.9,64.693 h1.4 r90
  text "D15 / SCL" at 52.7,64.3 h1.4 r90
  text "D8" at 29.1,63.7 h1.4 r90
  text "D6" at 22.5,57.869 h1.4 r90
  text "D2" at 12.3,56.7 h1.4 r90
  text "D4" at 17.4,56.7 h1.4 r90
  text "D0 / Rx" at 7.9,56.4 h1.4 r90
  text "D1 / Tx" at 10.4,56.4 h1.4 r90
  text "D3 / PWM" at 15.3,56.4 h1.4 r90
  text "D5 / PWM" at 20.5,56.4 h1.4 r90
  text "D7" at 25,56.4 h1.4 r90
  text "VREFP" at 46.9,56.4 h1.4 r90
  text "UK / CA" at 62.425,38.875 h5
  text "G" at 63.175,30.3 h10
  text "F" at 11.675,27.35 h12
  text "I" at 6.25,18 h12
  text "A5" at 7.2,16.537 h1.5 r90
  text "A4" at 9.8,15.277 h1.5 r90
  text "A3" at 12.283,15.281 h1.5 r90
  text "A2" at 14.7,15.271 h1.5 r90
  text "A1" at 17.3,15.095 h1.5 r90
  text "A0" at 19.783,13.978 h1.5 r90
  text "IOREF" at 40.283,9.3 h1.5 r90
  text "3V3" at 35.183,8.3 h1.5 r90
  text "NRST" at 37.684,8.3 h1.4 r90
  text "VIN" at 25,8.199 h1.5 r90
  text "GND" at 27.483,8.2 h1.5 r90
  text "GND" at 30.1,8.2 h1.5 r90
  text "5V" at 32.6,8.2 h1.5 r90
  text "NC" at 42.783,8.2 h1.5 r90
  text "E" at 21.525,2.125 h12
  text "H" at 13.1,0.35 h12
Top Solder:
  rectangle: 62.5,45.375 68.625,47.125
Bottom Solder:
  rectangle: 62.5,45.375 68.625,47.125
M1-Board Shape:
  lines w0.1: 0,1.5 0,1 ccw(c1,1) 1,0 69,0 ccw(c69,1) 70,1 70,69 ccw(c69,69) 69,70 1,70 ccw(c1,69) 0,69 0,1.5 ; 0,1.5 0,1.5
Drill Drawing:
  drawing of 317 lines, arcs and shapes, not listed
  text "THE COMPONENTS WITH PLATED THROUGH HOLE (PTH) MAY BE WELDED (CABLED) IN \"PIN-IN-PASTE\" MODE (IF NECESSARY)" at -62.125,120.625 h3
  text "PCB SPECIFICATIONS :" at -61.425,115.4 h3
  text "Layer" at 89.929,113.875 h2
  text "Name" at 98.303,113.875 h2
  text "Material" at 114.5,113.875 h2
  text "Thickness" at 129.871,113.875 h2
  text "Constant" at 141.826,113.875 h2
  text "MINIMUM PARAMETERS" at 158.15,113.867 h3
  text "A.   MATERIAL :" at -61.425,111.4 h3
  text "FR-4" at -22.925,111.4 h3
  text "TG-170" at -6.425,111.4 h3
  text "X  TG-150" at 11.825,111.4 h3
  text "TG-140" at 27.825,111.4 h3
  text "Top Overlay" at 98.303,109.875 h2
  text "B.   MATERIAL FAMILY :" at -61.425,108.4 h3
  text "N/A" at -22.925,108.4 h3
  text "DEFAULT" at 158.15,108.367 h3
  text "Top Solder" at 98.303,105.875 h2
  text "Solder Resist" at 114.5,105.875 h2
  text "0.020mm" at 129.871,105.875 h2
  text "3.5" at 141.826,105.875 h2
  text "C.   SOLDERMASK COLOR :" at -61.425,105.4 h3
  text "GREEN" at -22.925,105.4 h3
  text "X  BLUE" at -6.425,105.4 h3
  text "RED" at 11.825,105.4 h3
  text "BLACK" at 27.825,105.4 h3
  text "TRACKS : 0.12mm           / GAPS : 0.12mm" at 158.15,102.617 h3
  text "D.   SILKSCREEN COLOR :" at -61.425,102.4 h3
  text "X  WHITE" at -22.925,102.4 h3
  text "YELLOW" at -6.425,102.4 h3
  text "BLACK" at 11.825,102.4 h3
  text "1" at 89.929,101.875 h2
  text "Top Layer" at 98.303,101.875 h2
  text "0.054mm" at 129.871,101.875 h2
  text "E.   SURFACE FINISH :" at -61.425,99.4 h3
  text "X  ENIG" at -22.925,99.4 h3
  text "IMMERSION SILVER" at -6.425,99.4 h3
  text "IMMERSION TIN" at 27.825,99.4 h3
  text "Dielectric 1" at 98.303,97.875 h2
  text "1080HR RC68" at 114.5,97.875 h2
  text "0.076mm" at 129.871,97.875 h2
  text "4.2" at 141.826,97.875 h2
  text "HASL" at -22.925,96.4 h3
  text "HASL (PB-FREE)" at -6.425,96.4 h3
  text "GOLDEN FINGER" at 27.825,96.4 h3
  text "PCB : TYPE 3" at 159.378,94.081 h3
  text "2" at 89.928,93.875 h2
  text "Signal Layer 1" at 98.303,93.875 h2
  text "0.035mm" at 129.871,93.875 h2
  text "F.   IMPEDANCE CONTROL :" at -61.425,93.4 h3
  text "NO" at -22.925,93.4 h3
  text "X  YES  (SEE XLS FILE FOR DETAIL INFORMATION)" at -6.425,93.4 h3
  text "G.   THROUGH VIA :" at -61.425,90.4 h3
  text "PLUG THE VIAS WHICH ARE COVERED WITH SOLDERMASK ONE OR TWO SIDE." at -22.925,90.4 h3
  text "Dielectric 2" at 98.303,89.875 h2
  text "FR4" at 114.5,89.875 h2
  text "1.230mm" at 129.871,89.875 h2
  text "4.5" at 141.826,89.875 h2
  text "ASPECT-RATIO, AXE Z :" at 159.378,88.581 h3
  text "PLUG MATERIAL :" at -22.925,87.4 h3
  text "X  SOLDERMASK" at 2.575,87.4 h3
  text "NON-CONDUCTIVE EPOXY." at 27.825,87.4 h3
  text "3" at 89.929,85.875 h2
  text "Signal Layer 2" at 98.303,85.875 h2
  text "0.035mm" at 129.871,85.875 h2
  text "H.   STACK-UP :" at -61.425,84.4 h3
  text "SEE LAYER STACK-UP SEQUENCE FOR OVERALL THICKNESS." at -22.925,84.4 h3
  text "Dielectric 3" at 98.303,81.875 h2
  text "1080HR RC68" at 114.5,81.875 h2
  text "0.076mm" at 129.871,81.875 h2
  text "4.2" at 141.826,81.875 h2
  text "4" at 89.929,77.875 h2
  text "Bottom Layer" at 98.303,77.875 h2
  text "0.054mm" at 129.871,77.875 h2
  text "Bottom Solder" at 98.303,73.875 h2
  text "Solder Resist" at 114.5,73.875 h2
  text "0.020mm" at 129.871,73.875 h2
  text "3.5" at 141.826,73.875 h2
  text "DEFAULT / < 6:1 / LEVEL \"A\" /  / STLink / > 8 : 1 / LEVEL \"C\"" at 159.25,70.625 h3
  text "Bottom Overlay" at 98.303,69.875 h2
  text "Symbol" at 88.258,59.217 h2.4
  text "Count" at 97.657,59.217 h2.4
  text "Hole Size" at 107.42,59.217 h2.4
  text "Plated" at 125.719,59.217 h2.4
  text "Hole Type" at 133.97,59.217 h2.4
  text "Drill Layer Pair" at 145.981,59.217 h2.4
  text "Via/Pad" at 168.761,59.217 h2.4
  text "Pad Shape" at 178.604,59.217 h2.4
  text "54" at 97.657,55.074 h2
  text "0.200mm (7.87mil)" at 107.42,55.074 h2
  text "PTH" at 125.719,55.074 h2
  text "Round" at 133.97,55.074 h2
  text "Top Layer - Bottom Layer" at 145.981,55.074 h2
  text "Via" at 168.761,55.074 h2
  text "Rounded" at 178.604,55.074 h2
  text "A" at 87.47,54.82 h1.84
  text "509" at 97.657,50.931 h2
  text "0.300mm (11.81mil)" at 107.42,50.931 h2
  text "PTH" at 125.719,50.931 h2
  text "Round" at 133.97,50.931 h2
  text "Top Layer - Bottom Layer" at 145.981,50.931 h2
  text "Via" at 168.761,50.931 h2
  text "Rounded" at 178.604,50.931 h2
  text "14" at 97.657,46.788 h2
  text "0.400mm (15.75mil)" at 107.42,46.788 h2
  text "PTH" at 125.719,46.788 h2
  text "Round" at 133.97,46.788 h2
  text "Top Layer - Bottom Layer" at 145.981,46.788 h2
  text "Pad" at 168.761,46.788 h2
  text "Rounded" at 178.604,46.788 h2
  text "3" at 97.657,42.645 h2
  text "0.450mm (17.72mil)" at 107.42,42.645 h2
  text "PTH" at 125.719,42.645 h2
  text "Slot" at 133.97,42.645 h2
  text "Top Layer - Bottom Layer" at 145.981,42.645 h2
  text "Pad" at 168.761,42.645 h2
  text "Rounded" at 178.604,42.645 h2
  text "1" at 97.657,38.502 h2
  text "0.450mm (17.72mil)" at 107.42,38.502 h2
  text "PTH" at 125.719,38.502 h2
  text "Slot" at 133.97,38.502 h2
  text "Top Layer - Bottom Layer" at 145.981,38.502 h2
  text "Pad" at 168.761,38.502 h2
  text "Rounded" at 178.604,38.502 h2
  text "1" at 97.657,34.359 h2
  text "0.500mm (19.69mil)" at 107.42,34.359 h2
  text "NPTH" at 125.719,34.359 h2
  text "Round" at 133.97,34.359 h2
  text "Top Layer - Bottom Layer" at 145.981,34.359 h2
  text "Pad" at 168.761,34.359 h2
  text "Rounded" at 178.604,34.359 h2
  text "3" at 97.657,30.215 h2
  text "0.800mm (31.50mil)" at 107.42,30.215 h2
  text "NPTH" at 125.719,30.215 h2
  text "Round" at 133.97,30.215 h2
  text "Top Layer - Bottom Layer" at 145.981,30.215 h2
  text "Pad" at 168.761,30.215 h2
  text "Rounded" at 178.604,30.215 h2
  text "2" at 97.657,26.072 h2
  text "0.800mm (31.50mil)" at 107.42,26.072 h2
  text "PTH" at 125.719,26.072 h2
  text "Round" at 133.97,26.072 h2
  text "Top Layer - Bottom Layer" at 145.981,26.072 h2
  text "Pad" at 168.761,26.072 h2
  text "(Mixed)" at 178.604,26.072 h2
  text "20" at 97.657,21.929 h2
  text "0.900mm (35.43mil)" at 107.42,21.929 h2
  text "PTH" at 125.719,21.929 h2
  text "Round" at 133.97,21.929 h2
  text "Top Layer - Bottom Layer" at 145.981,21.929 h2
  text "Pad" at 168.761,21.929 h2
  text "(Mixed)" at 178.604,21.929 h2
  text "2" at 97.657,17.786 h2
  text "0.970mm (38.19mil)" at 107.42,17.786 h2
  text "NPTH" at 125.719,17.786 h2
  text "Round" at 133.97,17.786 h2
  text "Top Layer - Bottom Layer" at 145.981,17.786 h2
  text "Pad" at 168.761,17.786 h2
  text "Rounded" at 178.604,17.786 h2
  text "26" at 97.657,13.643 h2
  text "1.000mm (39.37mil)" at 107.42,13.643 h2
  text "PTH" at 125.719,13.643 h2
  text "Round" at 133.97,13.643 h2
  text "Top Layer - Bottom Layer" at 145.981,13.643 h2
  text "Pad" at 168.761,13.643 h2
  text "Rounded" at 178.604,13.643 h2
  text "4" at 97.657,9.5 h2
  text "1.100mm (43.31mil)" at 107.42,9.5 h2
  text "NPTH" at 125.719,9.5 h2
  text "Round" at 133.97,9.5 h2
  text "Top Layer - Bottom Layer" at 145.981,9.5 h2
  text "Pad" at 168.761,9.5 h2
  text "Rounded" at 178.604,9.5 h2
  text "2" at 97.657,5.357 h2
  text "1.190mm (46.85mil)" at 107.42,5.357 h2
  text "NPTH" at 125.719,5.357 h2
  text "Round" at 133.97,5.357 h2
  text "Top Layer - Bottom Layer" at 145.981,5.357 h2
  text "Pad" at 168.761,5.357 h2
  text "Rounded" at 178.604,5.357 h2
  text "4" at 97.657,1.214 h2
  text "2.000mm (78.74mil)" at 107.42,1.214 h2
  text "NPTH" at 125.719,1.214 h2
  text "Round" at 133.97,1.214 h2
  text "Top Layer - Bottom Layer" at 145.981,1.214 h2
  text "Pad" at 168.761,1.214 h2
  text "Rounded" at 178.604,1.214 h2
  text "645 Total" at 97.657,-2.929 h2
  text "Slot definitions :" at 88.258,-5.829 h2
  text "Routed Path Length" at 101.911,-5.829 h2
  text "= Calculated from tool start centre position to tool end centre position." at 118.824,-5.829 h2
  text "Hole Length" at 101.911,-7.487 h2
  text "= Routed Path Length + Tool Size = Slot length as defined in the PCB layout" at 112.545,-7.487 h2

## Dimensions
0,69 to 70,68.775 on M2-Board Dimensions
0,70 to 0,0 on M2-Board Dimensions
